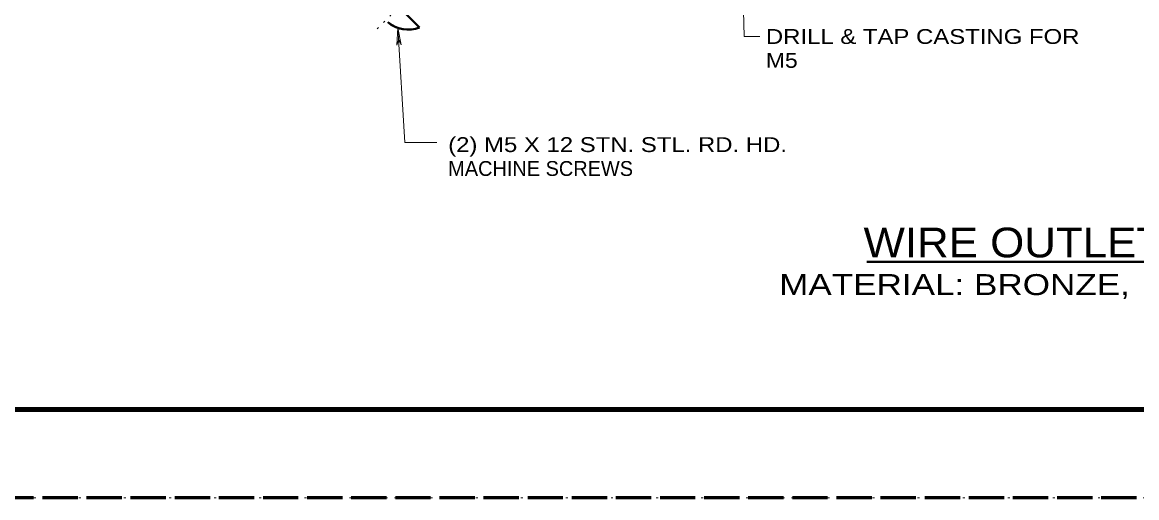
# Model space of a CAD drawing. Extents: x 312583 to 312854, y 144419 to 144597.
# Drawn here: x 312617.2 to 312674, y 144418.6 to 144442.9 of the extents above; entities that cross this region are included whole.
import ezdxf
from ezdxf.enums import TextEntityAlignment as Align

# ---------------------------------------------------------------- set-up
doc = ezdxf.new("R2010")
doc.units = 0
doc.header["$LTSCALE"] = 0.3
doc.linetypes.add('DOTTED', pattern=[1.5, 0.3, -1.2])
doc.linetypes.add('LONG_DASHED', pattern=[7.5, 6, -1.5])
for name, color, linetype, lineweight in [('1', 7, 'Continuous', 40), ('2', 7, 'Continuous', 13), ('62', 7, 'DOTTED', 13), ('63', 7, 'LONG_DASHED', 60)]:
    doc.layers.add(name, color=color, linetype=linetype, lineweight=lineweight)

msp = doc.modelspace()

# ---------------------------------------------------------------- linework, layer by layer
at = {"layer": '1', "linetype": 'DOTTED', "lineweight": 13}
msp.add_line((312640.8727, 144448.1379), (312635.1994, 144442.4646), dxfattribs=at)
at = {"layer": '1'}
msp.add_line((312635.3297, 144444.6956), (312637.4304, 144442.5949), dxfattribs=at)
at = {"layer": '1', "lineweight": 158}
msp.add_line((312616.5, 144423.0846), (312849, 144423.0846), dxfattribs=at)
at = {"layer": '1'}
for start in [230.34484, 232.25658]:
    msp.add_arc((312636.8603, 144444.1255), 1.6333, start, 290.42817, dxfattribs=at)
at = {"layer": '2'}
for p, q in [((312653.6971, 144454.5856), (312653.9904, 144442.1502)), ((312636.334, 144442.5796), (312636.2804, 144441.7056)), ((312636.334, 144442.5796), (312636.495, 144441.7209)), ((312653.9904, 144442.1502), (312654.7877, 144442.1502)), ((312636.2804, 144441.7056), (312636.3724, 144441.9892)), ((312636.495, 144441.7209), (312636.3724, 144441.9892))]:
    msp.add_line(p, q, dxfattribs=at)
at = {"layer": '2', "lineweight": 40}
msp.add_line((312660.246, 144430.6272), (312675.0928, 144430.6272), dxfattribs=at)
at = {"layer": '2'}
msp.add_lwpolyline([(312636.334, 144442.5796), (312636.6867, 144436.7299), (312638.312, 144436.7299)], dxfattribs=at)
at = {"layer": '62'}
msp.add_lwpolyline([(312601.2, 144418.5846), (312853.5, 144418.5846), (312853.5, 144596.7846)], dxfattribs=at)
at = {"layer": '63'}
msp.add_line((312851.75, 144418.5846), (312583.526, 144418.5846), dxfattribs=at)

# ---------------------------------------------------------------- texts
at = {"layer": '2'}
for s, width, p in [('DRILL & TAP CASTING FOR', 1.2, (312655.0983, 144441.7622)), ('M5 ', 1.15, (312655.0983, 144440.5422)), ('(2) M5 X 12 STN. STL. RD. HD.', 1.2, (312638.8949, 144436.2402))]:
    msp.add_text(s, height=0.76, dxfattribs=dict(at, width=width)).set_placement(p)
msp.add_text('MACHINE SCREWS', height=0.76, dxfattribs=at).set_placement((312638.8949, 144435.0202))
for s, height, width, p in [('WIRE OUTLET', 1.52, 1.1, (312667.7189, 144430.8612)), ('MATERIAL: BRONZE,  85-5-5-5', 1.07, 1.25, (312668.5974, 144428.9363))]:
    msp.add_text(s, height=height, dxfattribs=dict(at, width=width)).set_placement(p, align=Align.CENTER)

doc.saveas('drawing.dxf')
